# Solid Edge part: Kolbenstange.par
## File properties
Last saved by: ahadarics
Revision: 77
Dokumentum tartalom típus: 0
Sűrűség: 0,000 kg/m^3
Pontosság: 0,990
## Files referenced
..\AJ 63_10.asm
\\Fsrv2\user\tervezes\Solid Edge ST4\Zylinder\Hengermodellek 2024\Körprofil A\AJ\AJ_063_0010\Kit.par
rprofil A\AJ\AJ_063_0010\AJ 63_10.asm
rprofil A\AJ\AJ_063_0010\Kit.par
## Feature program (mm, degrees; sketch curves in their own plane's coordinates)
base feature "unnamed BaseFeature 1"
sketch for "unnamed Protrusion 1" plane through (0, 0, -78.25) normal (0, 0, -1) x-axis (0, 1, 0)
  circle centre (0, 0) radius 31.5
extrude "unnamed Protrusion 1" add to key point along -normal
thread "unnamed Thread 1"
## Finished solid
Body 1: solid body, 16 faces, 26 edges, 12 vertices.
  Faces by surface: plane 7, cylinder 4, torus 3, cone 2
  Edges by curve: circle 12, intersection 6, line 6, ellipse 2
Bounding box of the edges (mm; curved faces can reach further): 63.000 x 63.000 x 154.000, from (-31.5, -31.5, -78.25) to (31.5, 31.5, 75.75).
Cylindrical faces by radius (mm): R8 x1, R9.5 x1, R10 x1, R31.5 x1
Conical faces (half-angle, radius in mm at the cone's reference point): 30 deg R9.75 x1, 45 deg R7.5 x1
Toroidal faces (ring radius, tube radius in mm): R9 r0.5 x2, R9 r1 x1
Planar faces by outward normal: +x 1, +z 2, -x 1, -z 1, oblique 2
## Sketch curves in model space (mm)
circle centre (0, 0, -78.25) radius 31.5
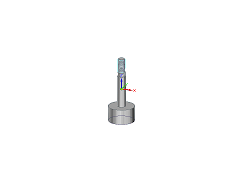
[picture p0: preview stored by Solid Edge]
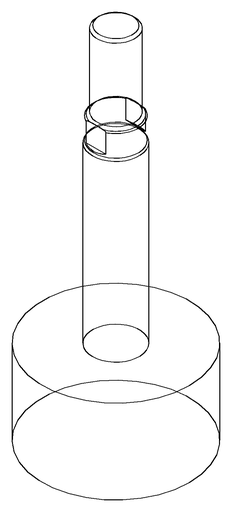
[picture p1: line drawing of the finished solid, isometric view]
